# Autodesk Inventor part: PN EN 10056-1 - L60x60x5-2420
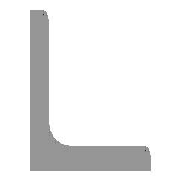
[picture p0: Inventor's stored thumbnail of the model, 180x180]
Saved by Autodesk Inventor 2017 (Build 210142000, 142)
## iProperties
IsCustomPart: 1
Created: 2016-02
Part Number: PN EN 10056-1 - L60x60x5-2420
Material: Stal, miękka
Description: Kątownik równoramienny
Document SubType Name: Modeling
Standard: PN
Designer: X
Standards Organization: PN
Language: pl-PL
Size Designation: L60x60x5
Categories: <MemberInstance><Categories><Category DisplayName="Kształtowniki konstrukcyjne" InternalName="089c4875-fa83-4c05-b084-43b9cc11f5ed" Mnemonic="GRDR"><CategoryPar
Stock Number: L60x60x5
Density: 7.85 g/cm^3
Appearance: Częściowo polerowana
Mass: 11053.7 g
Surface Area: 5653.45 cm^2
Volume: 1408.12 cm^3
_CCFamilyMember: 130
_CCFamilyDisplayName: PN EN 10056-1 (Kątownik równoramienny) - Kątownik równoramienny
_FrameMemberDoc: Frame Member File
_Version: 15.0.0
_GetPNFromCC: 1
G_W: 60,000 mm
G_H: 60,000 mm
G_L: 2420,000 mm
Author: X
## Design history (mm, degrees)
node "Płaszczyzna początkowa"
node "Płaszczyzna końcowa"
sketch "Szkic"
  geometry: L1 (-11.517, -3.517)-(-11.517, 39.483); L2 (-16.517, 43.483)-(-15.517, 43.483); L3 (-16.517, -16.517)-(-16.517, 43.483); L4 (-16.517, -16.517)-(43.483, -16.517); L5 (43.483, -15.517)-(43.483, -16.517); L6 (-3.517, -11.517)-(39.483, -11.517); L7 (0, 56.477)-(0, -28.683) reference; L8 (-28.683, 0)-(56.477, 0) reference; A1 r 8 centre (-3.517, -3.517) between (-11.517, -3.517) and (-3.517, -11.517); A2 r 4 centre (-15.517, 39.483) between (-11.517, 39.483) and (-15.517, 43.483); A3 r 4 centre (39.483, -15.517) between (43.483, -15.517) and (39.483, -11.517); 3 further points
  constraints: 12 end point, 6 point on circle, 6 point on line, 6 tangent, 3 centre point, 3 horizontal, 3 vertical, 1 equal radius
  dimensions: "d4" = 60 distance of L3.start L4.end (= b); "d6" = 60 distance of L3.start L2.start (= b); "d8" = 5 distance of point (43.483, -11.517) L4.end (= ParT); "d10" = 5 distance of L2.start point (-11.517, 43.483) (= ParT); "d17" = 8 radius of A1 (= R); "d18" = 4 radius of A2 (= R1); "d19" = 16.51748 distance between parallel lines of L8 L4 (= ex); "d20" = 16.51748 distance between parallel lines of L3 L7 (= d19)
extrude "Bryła" new body sketch "Szkic" stored distance "d11" = 2420 (= G_L); taper "d12" = 0 deg
node "Driven Length"
  sketch "Sketch3"
    geometry: L1 (0, 0)-(10, 0) reference
    constraints: 2 end point, 1 horizontal
  workplane "Work Plane10"
  sketch "Sketch4"
    geometry: L1 (-2, -60)-(12, -60) reference; L2 (-2, 2360)-(12, 2360) reference
    dimensions: "d24" = 2420 distance between parallel lines of L1 L2 (derived)
body "Solid1"
other parameters: "b" = 60 [user parameter; used in 3 equation terms], "ParT" = 5 [user parameter; used in 3 equation terms], "R" = 8 [user parameter; used in 1 equation term], "R1" = 4 [user parameter; used in 1 equation term], "G_L" = 2420 (= d24) [user parameter; used in 1 equation term], "d7" = 4 (derived), "d9" = 4 (derived), "ex" = 16.51748 (computed from b, ParT) [user parameter; used in 1 equation term], "d23" = 90 deg
